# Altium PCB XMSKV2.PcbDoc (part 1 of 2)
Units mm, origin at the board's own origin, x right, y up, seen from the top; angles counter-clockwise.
Board outline 142.11 x 151.76 mm, 2 copper layers (Top Layer, Bottom Layer); 107 components, 86 nets, 501 pads, 0 vias.
Unrouted connection lines stored in the file: 29.
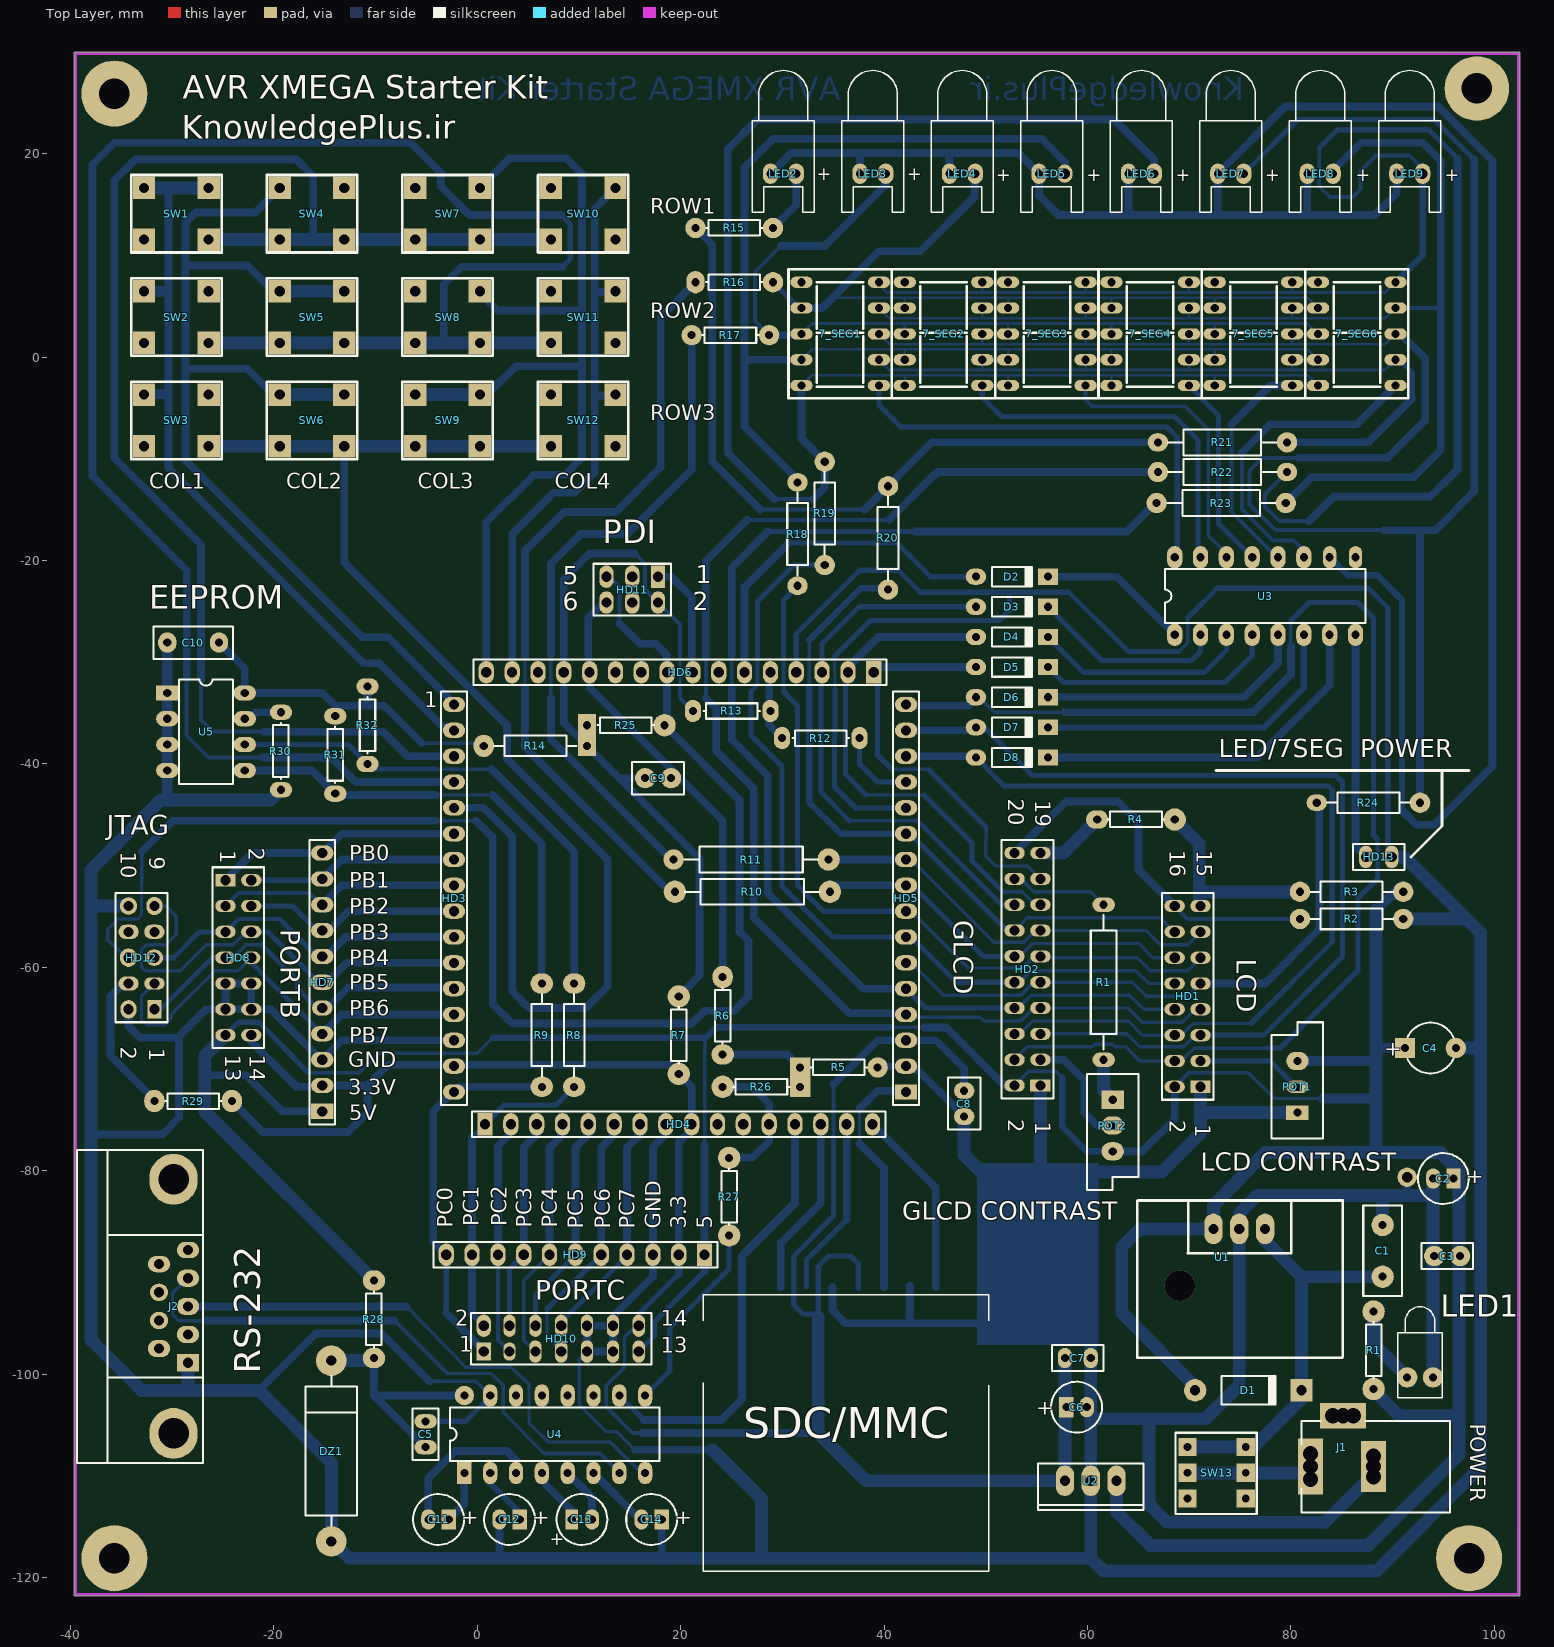
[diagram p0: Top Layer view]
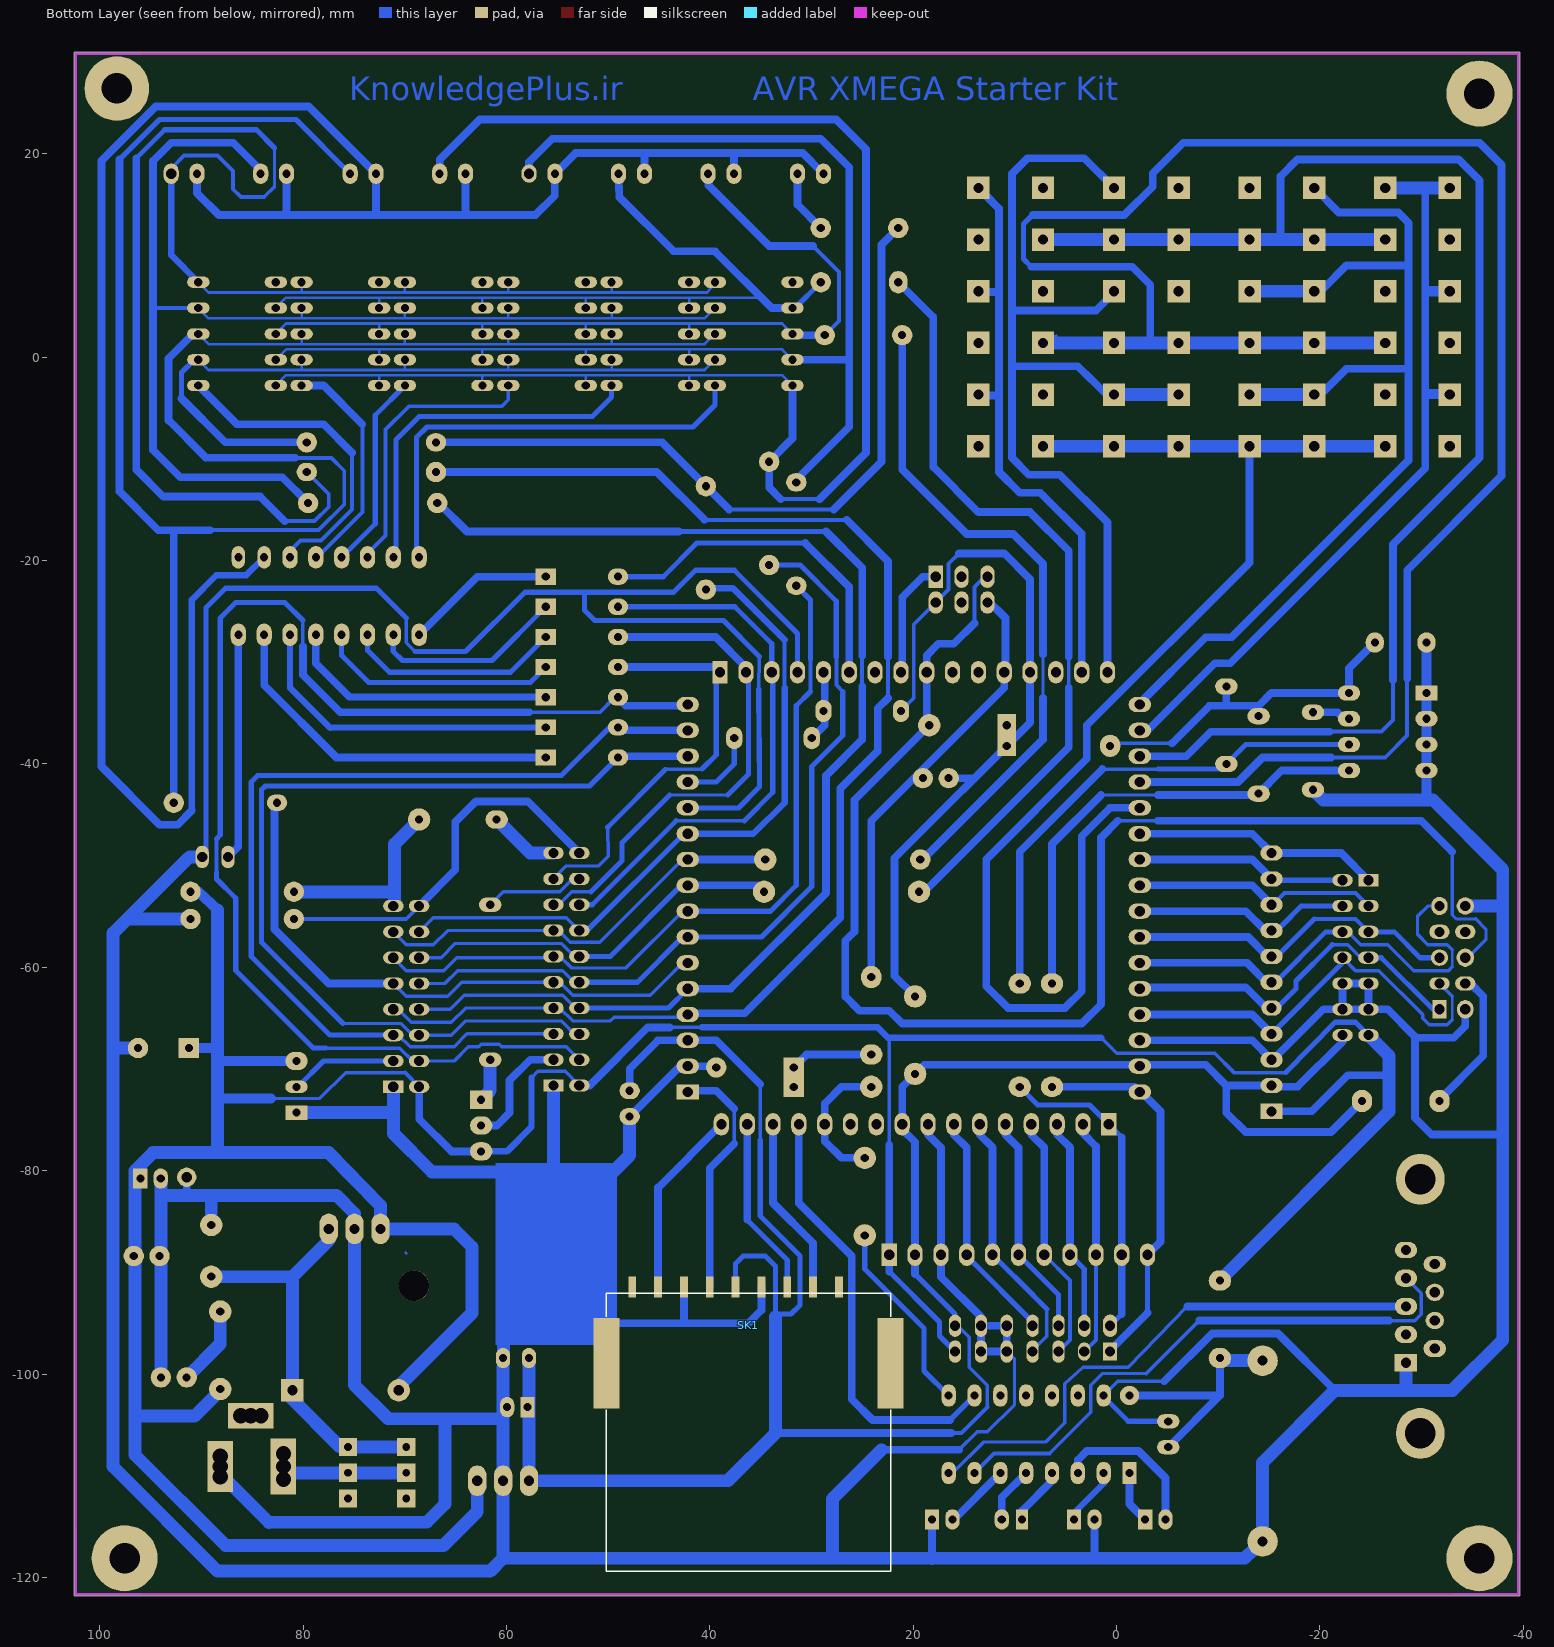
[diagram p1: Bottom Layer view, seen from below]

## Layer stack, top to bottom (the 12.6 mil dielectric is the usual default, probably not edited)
Top Layer: signal copper 0.0356
Dielectric: dielectric 0.32, FR-4, Dk 4.8
Bottom Layer: signal copper 0.0356

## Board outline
-39.624,-121.793 102.489,-121.793 102.489,29.972 -39.624,29.972

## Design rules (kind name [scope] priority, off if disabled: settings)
Clearance [All] p1: gap=0.254
PlaneClearance PlaneClearance_1 [HasPad('SW13-0')] p1: clearance=0.254
PlaneClearance [All] p2: clearance=0.508
PolygonConnect [All] p1: connectstyle=Relief reliefconductorwidth=0.254 reliefentries=4 polygonreliefangle="90 Angle" airgapwidth=0.254
RoutingPriority [All] p1: routingpriority=4
RoutingVias [All] p1: holewidth=0.508 width=1.27 viastyle="Through Hole" minholewidth=0.711 minwidth=1.27 maxholewidth=0.711 maxwidth=1.27
SolderMaskExpansion SolderMaskExpansion_1 [HasPad('SW13-0')] p1: expansion=0.051
SolderMaskExpansion [All] p2: expansion=0.102
Width [All] p1: maxlimit=2.54 minlimit=2.54 preferedwidth=0.254
26 further rules are at their usual default settings.

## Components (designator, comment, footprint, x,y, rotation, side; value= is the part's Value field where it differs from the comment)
7_SEG1 "Common cathode" 7_SEG 31.877,7.366 r0 top
7_SEG2 "Common cathode" 7_SEG 42.037,7.366 r0 top
7_SEG3 "Common cathode" 7_SEG 52.197,7.366 r0 top
7_SEG4 "Common cathode" 7_SEG 62.357,7.366 r0 top
7_SEG5 "Common cathode" 7_SEG 72.517,7.366 r0 top
7_SEG6 "Common cathode" 7_SEG 82.677,7.366 r0 top
C1 "330nF" RAD-0.2 89.027,-87.884 r270 top
C2 "10uF/16v/Tantalium" CAPPR2-5X6.8#1 94.996,-80.772 r180 top
C3 "100nF" RAD-0.1#1 95.377,-88.392 r180 top
C4 "1000uF/16v" CAPPR5-5X5 93.726,-67.945 r0 top
C5 "100nF" RAD-0.1#2 -5.08,-105.918 r90 top
C6 "10uF/16v/Tantalium" CAPPR2-5X6.8#1 58.928,-103.251 r0 top
C7 "100nF" RAD-0.1#3 59.055,-98.425 r0 top
C8 "100nF" CAPR2.54-5.1#1 47.879,-73.406 r270 top
C9 "100nF" CAPR2.54-5.1#2 17.78,-41.402 r180 top
C10 "100nF" CAPR5.08-7.8 -27.94,-28.067 r180 top
C11 "1uF" CAPPR2-5X6.8#1 -3.81,-114.3 r180 top
C12 "1uF" CAPPR2-5X6.8#1 3.175,-114.3 r180 top
C13 "1uF" CAPPR2-5X6.8#2 10.287,-114.3 r0 top
C14 "1uF" CAPPR2-5X6.8#1 17.145,-114.3 r180 top
D1 "1N4001" DIO10.46-5.3 75.819,-101.6 r0 top
D2 "1N4148" DIO7.1-3.9x1#1 52.578,-21.59 r0 top
D3 "1N4148" DIO7.1-3.9x1#1 52.578,-24.553 r0 top
D4 "1N4148" DIO7.1-3.9x1#1 52.578,-27.517 r0 top
D5 "1N4148" DIO7.1-3.9x1#1 52.578,-30.48 r0 top
D6 "1N4148" DIO7.1-3.9x1#1 52.578,-33.443 r0 top
D7 "1N4148" DIO7.1-3.9x1#2 52.578,-36.407 r0 top
D8 "1N4148" DIO7.1-3.9x1#1 52.578,-39.37 r0 top
DZ1 "1N4735" DIODE-0.7 -14.351,-107.569 r90 top
HD1 "2x8 box header" HDR2X8 71.12,-71.755 r90 top
HD2 "2x10 box header" HDR2X10 55.372,-71.628 r90 top
HD3 "1x16 female pin header" header1x16#1 -2.286,-34.163 r90 top
HD4 "1x16 female pin header" header1x16#2 0.762,-75.438 r180 top
HD5 "1x16 female pin header" header1x16#2 42.164,-72.263 r270 top
HD6 "1x16 female pin header" header1x16#2 38.989,-30.988 r0 top
HD7 "1x11 round pin Header" HDR1X11#1 -15.24,-74.168 r90 top
HD8 "2x7 pin header" HDR2X7#1 -24.765,-51.435 r270 top
HD9 "1x11 round pin Header" HDR1X11#2 22.352,-88.265 r180 top
HD10 "2x7 pin header" HDR2X7#2 0.635,-97.79 r0 top
HD11 "2x3 box header" HDR2X3 17.78,-21.59 r180 top
HD12 "2x5 box header" HDR2X5 -31.75,-64.135 r90 top
HD13 "1x2 pin header + jumper" RAD-0.1#4 88.646,-49.149 r180 top
J1 "Adaptor jack" KLD-0202 95.631,-109.093 r180 top
J2 "9 pin male D-Connector" DSUB1.385-2H -39.37,-93.345 r90 top
LED1 "LED" LED-1 92.71,-100.33 r90 top
LED2 "LED" LED-0#1 30.099,18.034 r180 top
LED3 "LED" LED-0#1 38.898,18.034 r180 top
LED4 "LED" LED-0#1 47.698,18.034 r180 top
LED5 "LED" LED-0#2 56.497,18.034 r180 top
LED6 "LED" LED-0#1 65.296,18.034 r180 top
LED7 "LED" LED-0#1 74.095,18.034 r180 top
LED8 "LED" LED-0#1 82.895,18.034 r180 top
LED9 "LED" LED-0#3 91.694,18.034 r180 top
POT1 "20K Multiturn" VR5#1 80.645,-71.755 r90 top
POT2 "20K Multiturn" VR5#2 62.484,-75.565 r270 top
R1 "470 ohm" AXIAL-0.3#1 88.138,-97.663 r270 top
R1 "0 ohm" AXIAL-0.6#1 61.595,-61.468 r90 top
R2 "0 ohm" AXIAL-0.4#1 85.979,-55.245 r180 top
R3 "0 ohm" AXIAL-0.4#1 85.979,-52.578 r180 top
R4 "0 ohm" AXIAL-0.3#2 64.77,-45.466 r0 top
R5 "0 ohm" AXIAL-0.3#3 35.56,-69.85 r0 top
R6 "0 ohm" AXIAL-0.3#4 24.13,-64.77 r90 top
R7 "0 ohm" AXIAL-0.3#1 19.812,-66.675 r90 top
R8 "0 ohm" AXIAL-0.4#2 9.525,-66.675 r90 top
R9 "0 ohm" AXIAL-0.4#2 6.35,-66.675 r90 top
R10 "0 ohm" AXIAL-0.6#2 27.051,-52.578 r0 top
R11 "0 ohm" AXIAL-0.6#3 26.924,-49.403 r0 top
R12 "0 ohm" AXIAL-0.3#5 33.782,-37.465 r180 top
R13 "0 ohm" AXIAL-0.3#5 25.019,-34.798 r180 top
R14 "0 ohm" AXIAL-0.4#3 5.715,-38.227 r180 top
R15 "0 ohm" AXIAL-0.3#6 25.273,12.7 r0 top
R16 "82 ohm" AXIAL-0.3#7 25.273,7.366 r0 top
R17 "82 ohm" AXIAL-0.3#6 24.892,2.159 r0 top
R18 "82 ohm" AXIAL-0.4#4 31.496,-17.399 r90 top
R19 "82 ohm" AXIAL-0.4#1 34.163,-15.367 r90 top
R20 "82 ohm" AXIAL-0.4#1 40.386,-17.78 r90 top
R21 "0 ohm" AXIAL-0.5#1 73.279,-8.382 r0 top
R22 "82 ohm" AXIAL-0.5#2 73.279,-11.303 r0 top
R23 "82 ohm" AXIAL-0.5#3 73.152,-14.351 r0 top
R24 "82 ohm" AXIAL-0.4#5 87.63,-43.815 r0 top
R25 "10Kohm" AXIAL-0.3#8 14.605,-36.195 r180 top
R26 "1Kohm" AXIAL-0.3#9 27.94,-71.755 r0 top
R27 "560 ohm" AXIAL-0.3#1 24.765,-82.55 r90 top
R28 "0 ohm" AXIAL-0.3#10 -10.16,-94.615 r90 top
R29 "0 ohm" AXIAL-0.3#10 -27.94,-73.152 r180 top
R30 "0 ohm" AXIAL-0.3#11 -19.304,-38.735 r270 top
R31 "3.3Kohm" AXIAL-0.3#5 -13.97,-39.116 r90 top
R32 "3.3Kohm" AXIAL-0.3#5 -10.795,-36.195 r90 top
SK1 "mmc socket" SDC 29.845,-91.44 r180 bottom
SW1 "Push button" SW_P_B -25.781,11.557 r180 top
SW2 "Push button" SW_P_B -25.781,1.397 r180 top
SW3 "Push button" SW_P_B -25.781,-8.763 r180 top locked
SW4 "Push button" SW_P_B -12.446,11.557 r180 top
SW5 "Push button" SW_P_B -12.446,1.397 r180 top
SW6 "Push button" SW_P_B -12.446,-8.763 r180 top
SW7 "Push button" SW_P_B 0.889,11.557 r180 top
SW8 "Push button" SW_P_B 0.889,1.397 r180 top
SW9 "Push button" SW_P_B 0.889,-8.763 r180 top
SW10 "Push button" SW_P_B 14.224,11.557 r180 top
SW11 "Push button" SW_P_B 14.224,1.397 r180 top
SW12 "Push button" SW_P_B 14.224,-8.763 r180 top
SW13 "6pin push button" "6PIN PB" 69.85,-112.268 r0 top
U1 "7805 + Heatsink" 7805_H 77.47,-85.725 r180 top
U2 "LF33" ISOWATT220AB 60.325,-110.49 r180 top
U3 "ULN2003A" A16 77.47,-23.495 r0 top
U4 "MAX232" DIP-16 7.62,-105.918 r0 top
U5 "AT24c64 + socket8" 8P3 -26.67,-36.83 r270 top

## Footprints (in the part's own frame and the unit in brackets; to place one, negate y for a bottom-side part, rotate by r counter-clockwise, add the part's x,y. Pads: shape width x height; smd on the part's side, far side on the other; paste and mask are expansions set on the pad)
"6PIN PB" [mil]
  rect 70x70 hole 30: 0(0,0.79) 0(0,100.79) 0(0,200.79) 0(225,0.79) 0(225,100.79) 0(225,200.79)
  silkscreen extent -47,-59 268,256
7_SEG [mm]
  oval 2.2x1.1 hole 0.8: 1(0,0) 2(0,-2.54) 3(0,-5.08) 4(0,-7.62) 5(0,-10.16) 6(7.62,-10.16) 7(7.62,-7.62) 8(7.62,-5.08) 9(7.62,-2.54) 10(7.62,0)
  silkscreen extent -1.27,-11.43 8.89,1.27
8P3 [mm]
  rect 1.5x2.2 hole 0.8: 1(-3.81,-3.81)
  oval 1.5x2.2 hole 0.8: 2(-1.27,-3.81) 3(1.27,-3.81) 4(3.81,-3.81) 5(3.81,3.81) 6(1.27,3.81) 7(-1.27,3.81) 8(-3.81,3.81)
  silkscreen extent -5.15,-2.65 5.15,2.65
7805_H [mm]
  round 3 hole 3: 0(8.382,5.588)
  oval 1.8x3 hole 1: 1(0,0) 2(5.08,0) 3(2.54,0)
  Multi-Layer lines w0.254: 7.62,2.388 7.569,2.337
  silkscreen extent -7.62,-2.82 12.57,12.67
A16 [mm]
  oval 1.5x2.2 hole 0.8: 1(-8.89,-3.81) 2(-6.35,-3.81) 3(-3.81,-3.81) 4(-1.27,-3.81) 5(1.27,-3.81) 6(3.81,-3.81) 7(6.35,-3.81) 8(8.89,-3.81) 11(3.81,3.81) 12(1.27,3.81) 13(-1.27,3.81) 14(-3.81,3.81) 15(-6.35,3.81) 16(-8.89,3.81)
  oval 1.3x2.2 hole 0.8: 9(8.89,3.81) 10(6.35,3.81)
  silkscreen extent -9.85,-2.65 9.85,2.65
AXIAL-0.3#1 [mm]
  round 2.2 hole 0.8: 1(-3.81,0) 2(3.81,0)
  silkscreen extent -2.77,-0.76 2.77,0.76
AXIAL-0.3#2 [mm]
  oval 2.2x1.8 hole 0.8: 1(-3.81,0)
  round 2.2 hole 0.8: 2(3.81,0)
  silkscreen extent -2.77,-0.76 2.77,0.76
AXIAL-0.3#3 [mm]
  rect 2x2 hole 0.8: 1(-3.81,0)
  round 2 hole 0.8: 2(3.81,0)
  silkscreen extent -2.77,-0.76 2.77,0.76
AXIAL-0.3#4 [mm]
  oval 2x2.2 hole 0.8: 1(-3.81,0)
  oval 2.2x2 hole 0.8: 2(3.81,0)
  silkscreen extent -2.77,-0.76 2.77,0.76
AXIAL-0.3#5 [mm]
  oval 1.6x2.2 hole 0.8: 1(-3.81,0) 2(3.81,0)
  silkscreen extent -2.77,-0.76 2.77,0.76
AXIAL-0.3#6 [mm]
  round 2 hole 0.8: 1(-3.81,0) 2(3.81,0)
  silkscreen extent -2.77,-0.76 2.77,0.76
AXIAL-0.3#7 [mm]
  oval 1.8x2.2 hole 0.8: 1(-3.81,0)
  round 2 hole 0.8: 2(3.81,0)
  silkscreen extent -2.77,-0.76 2.77,0.76
AXIAL-0.3#8 [mm]
  round 2.2 hole 0.8: 1(-3.81,0)
  rect 1.8x2.2 hole 0.8: 2(3.81,0)
  silkscreen extent -2.77,-0.76 2.77,0.76
AXIAL-0.3#9 [mm]
  round 2.2 hole 0.8: 1(-3.81,0)
  rect 2x2 hole 0.8: 2(3.81,0)
  silkscreen extent -2.77,-0.76 2.77,0.76
AXIAL-0.3#10 [mm]
  oval 2x2.2 hole 0.8: 1(-3.81,0) 2(3.81,0)
  silkscreen extent -2.77,-0.76 2.77,0.76
AXIAL-0.3#11 [mm]
  oval 1.5x2.2 hole 0.8: 1(-3.81,0) 2(3.81,0)
  silkscreen extent -2.77,-0.76 2.77,0.76
AXIAL-0.4#1 [mm]
  round 2 hole 0.8: 1(-5.08,0) 2(5.08,0)
  silkscreen extent -4.06,-1.02 4.06,1.02
AXIAL-0.4#2 [mm]
  oval 2x2.2 hole 0.8: 1(-5.08,0) 2(5.08,0)
  silkscreen extent -4.06,-1.02 4.06,1.02
AXIAL-0.4#3 [mm]
  rect 1.8x2 hole 0.8: 1(-5.08,0)
  oval 2x2.2 hole 0.8: 2(5.08,0)
  silkscreen extent -4.06,-1.02 4.06,1.02
AXIAL-0.4#4 [mm]
  oval 1.8x2 hole 0.8: 1(-5.08,0) 2(5.08,0)
  silkscreen extent -4.06,-1.02 4.06,1.02
AXIAL-0.4#5 [mm]
  oval 2x1.6 hole 0.8: 1(-5.08,0)
  round 2 hole 0.8: 2(5.08,0)
  silkscreen extent -4.06,-1.02 4.06,1.02
AXIAL-0.5#1 [mm]
  oval 2x1.8 hole 0.8: 1(-6.35,0)
  round 2 hole 0.8: 2(6.35,0)
  silkscreen extent -5.33,-1.27 5.33,1.27
AXIAL-0.5#2 [mm]
  round 2 hole 0.8: 1(-6.35,0)
  oval 2x1.8 hole 0.8: 2(6.35,0)
  silkscreen extent -5.33,-1.27 5.33,1.27
AXIAL-0.5#3 [mm]
  round 2 hole 0.8: 1(-6.35,0) 2(6.35,0)
  silkscreen extent -5.33,-1.27 5.33,1.27
AXIAL-0.6#1 [mm]
  oval 1.4x2.2 hole 0.8: 1(-7.62,0) 2(7.62,0)
  silkscreen extent -6.6,-1.27 6.6,1.27
AXIAL-0.6#2 [mm]
  round 2.2 hole 0.8: 1(-7.62,0) 2(7.62,0)
  silkscreen extent -6.6,-1.27 6.6,1.27
AXIAL-0.6#3 [mm]
  round 2 hole 0.8: 1(-7.62,0)
  round 2.2 hole 0.8: 2(7.62,0)
  silkscreen extent -6.6,-1.27 6.6,1.27
CAPPR2-5X6.8#1 [mm]
  rect 1.4x2 hole 0.8: 1(-1,0)
  oval 1.4x2 hole 0.8: 2(1,0)
  silkscreen extent -2.5,-2.5 2.5,2.5
CAPPR2-5X6.8#2 [mm]
  rect 1.2x2 hole 0.8: 1(-1,0)
  oval 1.4x2 hole 0.8: 2(1,0)
  silkscreen extent -2.5,-2.5 2.5,2.5
CAPPR5-5X5 [mm]
  rect 2x2 hole 0.8: 1(-2.5,0)
  round 2 hole 0.8: 2(2.5,0)
  silkscreen extent -2.26,-2.5 2.27,2.5
CAPR2.54-5.1#1 [mm]
  oval 1.65x2 hole 0.8: 1(-1.27,0) 2(1.27,0)
  silkscreen extent -2.55,-1.6 2.55,1.6
CAPR2.54-5.1#2 [mm]
  round 2 hole 0.8: 1(-1.27,0) 2(1.27,0)
  silkscreen extent -2.55,-1.6 2.55,1.6
CAPR5.08-7.8 [mm]
  oval 1.8x2 hole 0.8: 1(-2.54,0) 2(2.54,0)
  silkscreen extent -3.9,-1.6 3.9,1.6
DIO7.1-3.9x1#1 [mm]
  oval 2x1.6 hole 0.8: 1(-3.55,0)
  rect 2x1.6 hole 0.8: 2(3.55,0)
  silkscreen extent -1.95,-0.95 2.05,0.95
DIO7.1-3.9x1#2 [mm]
  oval 2x1.6 hole 0.8: 1(-3.55,0)
  rect 2x1.5 hole 0.8: 2(3.55,0)
  silkscreen extent -1.95,-0.95 2.05,0.95
DIO10.46-5.3 [mm]
  round 2.2 hole 1: 1(-5.23,0)
  rect 2.2x2.2 hole 1: 2(5.23,0)
  silkscreen extent -2.65,-1.4 2.75,1.4
DIODE-0.7 [mm]
  round 3 hole 1: 1(-8.89,0) 2(8.89,0)
  silkscreen extent -7.37,-2.54 7.37,2.54
DIP-16 [mm]
  rect 1.4x2.2 hole 0.8: 1(-8.89,-3.81)
  oval 1.4x2.2 hole 0.8: 2(-6.35,-3.81) 3(-3.81,-3.81) 4(-1.27,-3.81) 5(1.27,-3.81) 6(3.81,-3.81) 7(6.35,-3.81) 8(8.89,-3.81) 9(8.89,3.81) 10(6.35,3.81) 11(3.81,3.81) 12(1.27,3.81) 13(-1.27,3.81) 14(-3.81,3.81) 15(-6.35,3.81)
  round 1.9 hole 0.8: 16(-8.89,3.81)
  silkscreen extent -10.3,-2.65 10.3,2.65
DSUB1.385-2H [mm]
  oval 5x4.76 hole 3: 0(-12.495,-9.5) 0(12.495,-9.5)
  oval 1.6x2.2 hole 1: 1(5.54,-10.92) 6(4.155,-8.08)
  oval 1.69x2.2 hole 1: 2(2.77,-10.92) 3(0,-10.92) 4(-2.77,-10.92) 9(-4.155,-8.08)
  rect 1.69x2.2 hole 1: 5(-5.54,-10.92)
  oval 1.69x1.8 hole 1: 7(1.385,-8.08) 8(-1.385,-8.08)
  silkscreen extent -15.4,-12.4 15.4,0
HDR1X11#1 [mm]
  rect 1.5x2.2 hole 1: 1(0,0)
  oval 1.5x2.2 hole 1: 2(2.54,0) 3(5.08,0) 4(7.62,0) 6(12.7,0) 7(15.24,0) 8(17.78,0) 9(20.32,0) 10(22.86,0) 11(25.4,0)
  oval 1.5x2 hole 1: 5(10.16,0)
  silkscreen extent -1.27,-1.27 26.67,1.27
HDR1X11#2 [mm]
  rect 1.5x2.2 hole 1: 1(0,0)
  oval 1.5x2.2 hole 1: 2(2.54,0) 3(5.08,0) 4(7.62,0) 5(10.16,0) 6(12.7,0) 7(15.24,0) 8(17.78,0) 9(20.32,0) 10(22.86,0) 11(25.4,0)
  silkscreen extent -1.27,-1.27 26.67,1.27
HDR2X3 [mm]
  rect 1.4x2.2 hole 1: 1(0,0)
  oval 1.4x2.2 hole 1: 2(0,2.54) 3(2.54,0) 4(2.54,2.54) 5(5.08,0) 6(5.08,2.54)
  silkscreen extent -1.27,-1.27 6.35,3.81
HDR2X5 [mm]
  rect 1.8x1.4 hole 1: 1(0,0)
  oval 1.8x1.6 hole 1: 2(0,2.54) 9(10.16,0)
  oval 1.2x2 hole 1: 3(2.54,0)
  oval 1.4x2 hole 1: 4(2.54,2.54) 7(7.62,0) 8(7.62,2.54)
  oval 1.6x1.7 hole 1: 5(5.08,0)
  oval 1.8x1.7 hole 1: 6(5.08,2.54)
  oval 1.727x1.7 hole 1: 10(10.16,2.54)
  silkscreen extent -1.27,-1.27 11.43,3.81
HDR2X7#1 [mm]
  rect 1.2x2 hole 1: 1(0,0)
  oval 1.2x2 hole 1: 2(0,2.54) 3(2.54,0) 4(2.54,2.54) 5(5.08,0) 6(5.08,2.54) 7(7.62,0) 9(10.16,0) 10(10.16,2.54) 11(12.7,0) 12(12.7,2.54) 13(15.24,0) 14(15.24,2.54)
  oval 1.2x1.8 hole 1: 8(7.62,2.54)
  silkscreen extent -1.27,-1.27 16.51,3.81
HDR2X7#2 [mm]
  rect 1.4x1.8 hole 1: 1(0,0)
  oval 1.4x2.2 hole 1: 2(0,2.54)
  oval 1.2x1.8 hole 1: 3(2.54,0)
  oval 1.2x2.2 hole 1: 4(2.54,2.54) 5(5.08,0) 6(5.08,2.54) 7(7.62,0) 8(7.62,2.54) 9(10.16,0) 10(10.16,2.54) 11(12.7,0) 12(12.7,2.54) 13(15.24,0) 14(15.24,2.54)
  silkscreen extent -1.27,-1.27 16.51,3.81
HDR2X8 [mm]
  rect 1.2x2 hole 1: 1(0,0)
  oval 1.2x2 hole 1: 2(0,2.54) 3(2.54,0) 4(2.54,2.54) 5(5.08,0) 6(5.08,2.54) 7(7.62,0) 9(10.16,0) 10(10.16,2.54) 11(12.7,0) 13(15.24,0) 14(15.24,2.54) 15(17.78,0) 16(17.78,2.54)
  silkscreen extent -1.27,-1.27 19.05,3.81
HDR2X10 [mm]
  rect 1.2x2 hole 1: 1(0,0)
  oval 1.2x2 hole 1: 2(0,2.54) 3(2.54,0) 4(2.54,2.54) 5(5.08,0) 6(5.08,2.54) 7(7.62,0) 9(10.16,0) 10(10.16,2.54) 11(12.7,0) 13(15.24,0) 14(15.24,2.54) 15(17.78,0) 16(17.78,2.54) 17(20.32,0) 18(20.32,2.54) 19(22.86,0) 20(22.86,2.54)
  silkscreen extent -1.27,-1.27 24.13,3.81
header1x16#1 [mm]
  oval 1.5x2.2 hole 1: 1(0,0) 2(-2.54,0) 3(-5.08,0) 4(-7.62,0) 5(-10.16,0) 6(-12.7,0) 7(-15.24,0) 8(-17.78,0) 9(-20.32,0) 10(-22.86,0) 11(-25.4,0) 12(-27.94,0) 13(-30.48,0) 14(-33.02,0) 15(-35.56,0) 16(-38.1,0)
  silkscreen extent -39.37,-1.27 1.27,1.27
header1x16#2 [mm]
  rect 1.5x2.2 hole 1: 1(0,0)
  oval 1.5x2.2 hole 1: 2(-2.54,0) 3(-5.08,0) 4(-7.62,0) 5(-10.16,0) 6(-12.7,0) 7(-15.24,0) 8(-17.78,0) 9(-20.32,0) 10(-22.86,0) 11(-25.4,0) 12(-27.94,0) 13(-30.48,0) 14(-33.02,0) 15(-35.56,0) 16(-38.1,0)
  silkscreen extent -39.37,-1.27 1.27,1.27
ISOWATT220AB [mm]
  oval 1.8x3 hole 1: 1(-2.54,0) 2(2.54,0) 3(0,0)
  silkscreen extent -5.2,-1.7 5.2,2.9
KLD-0202 [mm]
  rect 2.5x2.5 hole 1.5: 1(13.7,0) 2(7.5,0) 3(10.5,-5) 3A(9.5,-5) 3B(11.5,-5)
  rect 2.5x3 hole 1.5: 1A(13.7,-1.25) 1B(13.7,1.25) 2A(7.5,-1) 2B(7.5,1)
  silkscreen extent 0,-4.5 14.6,4.5
LED-0#1 [mm]
  oval 1.5x2 hole 0.8: 1(1.27,0) 2(-1.27,0)
  silkscreen extent -3.05,-10.16 3.05,3.81
LED-0#2 [mm]
  oval 1.5x2 hole 0.8: 1(1.27,0)
  oval 1.5x1.778 hole 1: 2(-1.27,0)
  silkscreen extent -3.05,-10.16 3.05,3.81
LED-0#3 [mm]
  oval 1.5x2 hole 0.8: 1(1.27,0)
  oval 1.5x2 hole 1: 2(-1.27,0)
  silkscreen extent -3.05,-10.16 3.05,3.81
LED-1 [mm]
  round 2 hole 0.8: 1(0,1.27) 2(0,-1.27)
  silkscreen extent -2,-2.2 6.95,2.2
RAD-0.1#1 [mm]
  round 2 hole 0.8: 1(-1.27,0) 2(1.27,0)
  silkscreen extent -2.54,-1.27 2.54,1.27
RAD-0.1#2 [mm]
  oval 1.4x2.2 hole 0.8: 1(-1.27,0) 2(1.27,0)
  silkscreen extent -2.54,-1.27 2.54,1.27
RAD-0.1#3 [mm]
  oval 1.4x2 hole 0.8: 1(-1.27,0) 2(1.27,0)
  silkscreen extent -2.54,-1.27 2.54,1.27
RAD-0.1#4 [mm]
  oval 1.3x2.2 hole 1: 1(-1.27,0) 2(1.27,0)
  silkscreen extent -2.54,-1.27 2.54,1.27
RAD-0.2 [mm]
  round 2.2 hole 0.8: 1(-2.54,0) 2(2.54,0)
  silkscreen extent -4.44,-1.91 4.44,1.91
SDC [mil]
  rect 100x350 smd: 0(-800,-295) 0(300,-295)
  rect 30x80 smd: 1(0,0) 2(-100,0) 3(-200,0) 4(-300,0) 5(-400,0) 6(-500,0) 7(-600,0) 8(-700,0) 9(100,0)
  silkscreen extent -800,-1100 300,-25
SW_P_B [mm]
  rect 2.2x2.2 hole 1: 1(0.635,0) 2(0.635,-5.08) 3(6.985,-5.08) 4(6.985,0)
  silkscreen extent -0.64,-6.35 8.26,1.27
VR5#1 [mm]
  rect 1.4x2.2 hole 0.8: 1(-2.54,0)
  oval 1.2x2.2 hole 0.8: 2(0,0)
  oval 1.8x2.2 hole 0.8: 3(2.54,0)
  silkscreen extent -5.08,-2.54 6.35,2.54
VR5#2 [mm]
  rect 1.8x2.2 hole 0.8: 1(-2.54,0)
  oval 1.8x2.2 hole 0.8: 2(0,0) 3(2.54,0)
  silkscreen extent -5.08,-2.54 6.35,2.54

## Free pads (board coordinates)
  round 6.5 hole 3: 1(-35.687,-118.11) 2(97.536,-118.11) 4(-35.687,25.908)
  round 6.35 hole 3: 3(98.298,26.416)
  round 1.905 hole 1: 5(91.44,-80.645)
  oval 2x1.2 hole 1: 6(68.58,-64.135) 7(68.58,-59.055) 8(52.832,-64.008)
  oval 2x1.27 hole 1: 9(52.832,-58.928)

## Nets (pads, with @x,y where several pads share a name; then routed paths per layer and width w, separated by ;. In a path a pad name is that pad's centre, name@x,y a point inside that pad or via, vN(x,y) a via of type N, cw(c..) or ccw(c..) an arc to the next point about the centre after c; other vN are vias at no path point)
3.3V: C6.1 C7.1 C8.1 C9.2 C10.1 HD3.15 HD4.9 HD5.3 HD5.13 HD6.5 HD6.13 HD7.2 HD8.14 HD9.2 HD10.14 HD11.2 HD12.4 R7.1 R7.2 R12.1 R12.2 R13.1 R13.2 R14.1 R14.2 R25.2 R29.1 R29.2 R31.2 U2.2 U5.8 | length 365.6
  Bottom Layer w0.33: -5.461,-37.973 R14.2@0.254,-37.973 ; 12.7,-103.251 12.7,-101.092 14.478,-99.314 14.478,-96.393 HD10.14@15.875,-94.996 ; 19.939,-32.512 19.939,-29.464
  Bottom Layer w0.381: 12.7,-103.251 15.24,-105.791 16.256,-105.791 ; 15.494,-19.304 16.51,-20.32 16.51,-22.86 19.939,-26.289 19.939,-29.464 ; 19.939,-32.512 19.939,-33.528 R13.2@21.209,-34.798 ; 35.041,-76.973 35.041,-71.512
  Bottom Layer w0.508: -22.225,-67.31 HD8.14@-22.225,-66.675 ; HD10.14@15.875,-95.25 15.875,-94.107 19.812,-90.17 ; 33.528,-94.361 33.528,-89.408 34.544,-88.392 36.703,-88.392 37.465,-89.154 37.465,-91.567 ; 33.528,-94.107 32.004,-94.107 31.115,-93.218 31.115,-88.392 35.041,-84.466 35.041,-76.973 ; R12.1@37.592,-37.465 37.592,-40.005 39.37,-41.783 HD5.13@41.656,-41.783
  Bottom Layer w0.762: HD12.4@-34.29,-61.595 -34.798,-61.595 -36.068,-62.865 -36.068,-68.707 R29.2@-31.623,-73.152 ; C10.1@-25.4,-28.067 -22.86,-30.607 U5.8@-22.86,-33.02 -15.24,-33.02 -13.97,-34.29 -9.144,-34.29 -5.461,-37.973 ; R29.1@-24.13,-73.152 -21.082,-76.2 -12.7,-76.2 -10.795,-74.295 -10.795,-71.755 ; -22.225,-67.31 -17.78,-71.755 HD7.2@-15.24,-71.755 ; HD7.2@-15.24,-71.628 -10.795,-71.628 -8.763,-69.596 18.923,-69.596 R7.1@19.812,-70.485 21.082,-71.755 21.082,-75.946 19.812,-77.216 19.812,-90.17 ; R14.1@10.795,-38.227 R25.2@10.795,-36.195 ; 14.097,-41.402 C9.2@16.51,-41.402 ; 15.494,-19.304 11.049,-19.304 8.509,-21.844 8.509,-35.941 21.844,-49.276 21.844,-60.833 R7.2@19.812,-62.865 ; 16.256,-105.791 33.528,-105.791 ; HD6.5@28.702,-30.988 28.702,-36.195 R12.2@29.972,-37.465 ; 35.041,-71.512 39.37,-67.183 HD5.3@41.91,-67.183 ; HD5.3@42.164,-67.183 45.085,-67.183 47.879,-69.977 C8.1@47.879,-72.136
  Bottom Layer w1.27: 33.528,-94.361 33.528,-105.791 38.227,-110.49 U2.2@57.785,-110.49 ; U2.2@57.785,-110.363 C7.1@57.785,-98.425
5V: C2.1 C3.1 C4.1 C5.1 D1.1 DZ1.2 HD1.2 HD1.15 HD2.2 HD2.19 HD7.1 HD8.13 HD9.1 HD10.13 POT1.3 POT2.3 R1.2@88.138,-101.473 R3.1 R3.2 R4.1 R4.2 R28.1 R28.2 U1.2 U2.1 U4.16 | length 433.8
  Bottom Layer w0.33: -16.637,-70.358 -11.557,-70.358 ; -9.652,-68.453 0,-68.453 1.524,-66.929 ; 22.352,-77.47 22.352,-66.929 ; 40.767,-65.913 43.942,-65.913 ; HD2.2@52.832,-71.628 54.229,-70.231 56.896,-70.231 57.531,-70.866 ; 69.977,-70.358 75.819,-70.358 78.359,-72.898 83.185,-72.898
  Bottom Layer w0.381: -11.557,-70.358 -9.652,-68.453 ; HD1.2@68.58,-71.755 69.977,-70.358
  Bottom Layer w0.508: HD8.13@-24.765,-66.675 -23.495,-65.405 -21.463,-65.405 -16.637,-70.358 ; HD10.13@15.875,-97.79 17.399,-96.266 17.399,-94.869 22.352,-89.916
  Bottom Layer w0.635: 1.524,-66.929 22.479,-66.929 23.495,-65.913 40.767,-65.913 ; 51.816,-71.628 HD2.2@52.832,-71.628 ; 57.531,-70.866 57.531,-75.692 59.944,-78.105 POT2.3@61.849,-78.105
  Bottom Layer w0.762: -26.797,-70.612 -22.733,-70.612 -19.177,-74.168 HD7.1@-15.24,-74.168 ; R28.1@-10.16,-98.425 -10.16,-102.108 ; C5.1@-5.08,-107.188 -10.16,-102.108 ; U4.16@-1.27,-102.108 -10.16,-102.108 ; 22.352,-89.916 22.352,-77.47 ; 43.942,-65.913 46.101,-65.913 51.816,-71.628 ; POT2.3@62.484,-78.105 65.405,-78.105 68.58,-74.93 HD1.2@68.58,-71.755 ; U2.1@62.865,-110.211 U2.1@63.005,-110.35
  Bottom Layer w1.016: POT1.3@80.645,-69.215 88.265,-69.215 ; 83.185,-72.898 88.138,-72.898 ; 88.265,-67.945 C4.1@91.226,-67.945 ; 88.392,-54.356 90.297,-52.578 R3.1@91.313,-52.578
  Bottom Layer w1.27: HD8.13@-24.765,-66.675 -26.797,-68.707 -26.797,-74.168 R28.2@-10.16,-90.805 ; DZ1.2@-14.351,-98.679 R28.1@-10.16,-98.679 ; HD2.19@55.372,-48.768 57.658,-48.768 R4.1@60.96,-45.466 ; U2.1@62.865,-110.617 62.865,-113.538 66.167,-116.84 87.63,-116.84 96.52,-107.95 96.52,-80.01 94.742,-78.232 77.47,-78.232 72.39,-83.439 U1.2@72.39,-85.725 65.151,-85.725 63.373,-87.503 63.373,-93.98 D1.1@70.97,-101.6 ; R4.2@68.58,-45.466 70.993,-47.879 70.993,-52.578 ; HD1.15@70.993,-53.848 70.993,-52.578 ; R3.2@81.153,-52.578 70.993,-52.578 ; R1.2@88.392,-101.854 90.678,-104.14 96.52,-104.14 ; 88.392,-77.978 88.392,-54.356
7SEG_A: 7_SEG1.10 7_SEG2.10 7_SEG3.10 7_SEG4.10 7_SEG5.10 7_SEG6.10 LED9.2 R22.2 | length 156.6
  Bottom Layer w0.254: 7_SEG1.10@39.497,7.366 39.497,7.239 40.259,6.35 89.281,6.35 7_SEG6.10@90.297,7.366 ; 49.657,6.477 7_SEG2.10@49.657,7.366 ; 59.817,6.477 7_SEG3.10@59.817,7.366 ; 69.977,6.477 7_SEG4.10@69.977,7.366 ; 80.137,6.477 7_SEG5.10@80.137,7.366
  Bottom Layer w0.33: 82.804,20.574 82.804,16.764 83.82,15.748
  Bottom Layer w0.381: R22.2@79.629,-11.303 77.47,-13.462 77.47,-14.732 78.867,-16.129 81.788,-16.129 ; 83.82,15.748 86.106,15.748 86.868,16.51 86.868,18.288 88.392,19.812 91.694,19.812 92.71,18.796 LED9.2@92.964,18.796
  Bottom Layer w0.508: 82.804,20.574 84.582,22.352 93.599,22.352 96.393,19.558
  Bottom Layer w0.635: 7_SEG6.10@90.297,7.366 92.964,10.033 LED9.2@92.964,18.034
  Bottom Layer w0.762: 81.788,-16.129 84.201,-13.716 93.726,-13.716 96.393,-11.049 96.393,19.558
7SEG_B: 7_SEG1.9 7_SEG2.9 7_SEG3.9 7_SEG4.9 7_SEG5.9 7_SEG6.9 LED8.2 R23.2 | length 118.1
  Bottom Layer w0.254: 7_SEG1.9@39.497,4.826 40.513,3.81 89.281,3.81 7_SEG6.9@90.297,4.826 ; 49.657,3.81 7_SEG2.9@49.657,4.826 ; 59.817,3.81 7_SEG3.9@59.817,4.826 ; 69.977,3.81 7_SEG4.9@69.977,4.826 ; 80.137,3.81 7_SEG5.9@80.137,4.826
  Bottom Layer w0.381: 7_SEG6.9@90.678,4.826 94.488,4.826
  Bottom Layer w0.508: LED8.2@84.165,18.034 LED8.2@84.165,18.379
  Bottom Layer w0.762: R23.2@79.502,-14.351 82.042,-11.811 92.075,-11.811 94.742,-9.144 94.742,19.304 92.964,21.082 86.868,21.082 LED8.2@84.165,18.379
7SEG_C: 7_SEG1.8 7_SEG2.8 7_SEG3.8 7_SEG4.8 7_SEG5.8 7_SEG6.8 LED7.2 R24.2 | length 199
  Bottom Layer w0.254: 7_SEG1.8@39.497,2.286 40.513,1.27 89.281,1.27 7_SEG6.8@90.297,2.286 ; 49.657,1.27 7_SEG2.8@49.657,2.286 ; 59.817,1.27 7_SEG3.8@59.817,2.286 ; 69.977,1.27 7_SEG4.8@69.977,2.286 ; 80.137,1.27 7_SEG5.8@80.137,2.286
  Bottom Layer w0.381: 80.772,-9.906 77.216,-9.906 75.946,-11.176 75.946,-14.478 78.486,-17.018 89.408,-17.018
  Bottom Layer w0.508: LED7.2@75.365,18.034 80.699,23.368 94.107,23.368 98.044,19.431
  Bottom Layer w0.762: 80.772,-9.906 89.535,-9.906 93.218,-6.223 93.218,-0.127 7_SEG6.8@90.678,2.413 ; 89.154,-17.018 94.234,-17.018 98.044,-13.208 98.044,19.431 ; R24.2@92.71,-43.815 92.71,-17.018
7SEG_D: 7_SEG1.5 7_SEG2.5 7_SEG3.5 7_SEG4.5 7_SEG5.5 7_SEG6.5 LED6.2 R19.2 | length 154.4
  Bottom Layer w0.254: 7_SEG1.5@31.877,-2.794 32.893,-1.778 81.661,-1.778 7_SEG6.5@82.677,-2.794 ; 7_SEG2.5@42.037,-2.794 42.037,-1.778 ; 7_SEG3.5@52.197,-2.794 52.197,-1.778 ; 7_SEG4.5@62.357,-2.794 62.357,-1.905 ; 7_SEG5.5@72.517,-2.794 72.517,-1.778
  Bottom Layer w0.381: 29.21,-13.97 33.02,-13.97
  Bottom Layer w0.762: 29.21,-13.97 24.638,-9.398 24.638,20.447 27.559,23.368 62.611,23.368 66.548,19.431 LED6.2@66.566,18.034 ; 7_SEG1.5@31.877,-2.794 31.877,-8.001 R19.2@34.163,-10.287 34.163,-12.827 33.02,-13.97
7SEG_DP: 7_SEG1.7 7_SEG2.7 7_SEG3.7 7_SEG4.7 7_SEG5.7 7_SEG6.7 LED2.2 R15.1 R15.2 R20.2 R21.1 R21.2 | length 152.5
  Bottom Layer w0.254: 7_SEG1.7@39.497,-0.254 40.513,-1.27 89.281,-1.27 7_SEG6.7@90.297,-0.254 ; 49.657,-1.27 7_SEG2.7@49.657,-0.254 ; 59.817,-1.143 7_SEG3.7@59.817,-0.254 ; 69.977,-1.27 7_SEG4.7@69.977,-0.254 ; 80.137,-1.27 7_SEG5.7@80.137,-0.254
  Bottom Layer w0.381: 27.813,-14.986 38.1,-14.986
  Bottom Layer w0.508: 7_SEG6.7@90.678,-0.254 91.948,-1.524 91.948,-4.064
  Bottom Layer w0.762: R15.1@21.463,12.7 23.114,11.049 23.114,-10.287 27.813,-14.986 ; R15.2@29.083,12.7 31.369,14.986 LED2.2@31.369,18.034 ; 38.1,-14.986 44.704,-8.382 R21.1@66.929,-8.382 ; R21.2@79.629,-8.382 87.63,-8.382 91.948,-4.064
7SEG_E: 7_SEG1.4 7_SEG2.4 7_SEG3.4 7_SEG4.4 7_SEG5.4 7_SEG6.4 LED5.2 R18.2 | length 128.4
  Bottom Layer w0.254: 7_SEG1.4@31.877,-0.254 32.893,0.762 81.661,0.762 7_SEG6.4@82.677,-0.254 ; 7_SEG2.4@42.037,-0.254 42.037,0.635 ; 7_SEG3.4@52.197,-0.254 52.197,0.762 ; 7_SEG4.4@62.357,-0.254 62.357,0.635 ; 7_SEG5.4@72.517,-0.254 72.517,0.635
  Bottom Layer w0.762: 26.416,-0.254 7_SEG1.4@31.877,-0.254 ; R18.2@31.496,-12.065 26.289,-6.858 26.289,18.669 29.083,21.463 55.499,21.463 57.785,19.177 LED5.2@57.767,18.034
7SEG_F: 7_SEG1.2 7_SEG2.2 7_SEG3.2 7_SEG4.2 7_SEG5.2 7_SEG6.2 LED4.2 R16.2 | length 79.4
  Bottom Layer w0.254: 34.925,5.842 81.661,5.842 7_SEG6.2@82.677,4.826 ; 7_SEG2.2@42.037,4.826 42.037,5.715 ; 7_SEG3.2@52.197,4.826 52.197,5.715 ; 7_SEG4.2@62.357,4.826 62.357,5.715 ; 7_SEG5.2@72.517,4.826 72.517,5.715
  Bottom Layer w0.381: 7_SEG1.2@31.623,4.826 7_SEG1.2@31.877,4.826
  Bottom Layer w0.508: R16.2@29.083,7.366 7_SEG1.2@31.623,4.826
  Bottom Layer w0.762: 7_SEG1.2@31.877,4.826 33.909,4.826 39.497,10.414 43.561,10.414 48.895,15.748 LED4.2@48.968,18.034
7SEG_G: 7_SEG1.3 7_SEG2.3 7_SEG3.3 7_SEG4.3 7_SEG5.3 7_SEG6.3 LED3.2 R17.2 | length 83.1
  Bottom Layer w0.254: 7_SEG1.3@31.877,2.286 32.893,3.302 81.661,3.302 7_SEG6.3@82.677,2.286 ; 7_SEG2.3@42.037,2.286 42.037,3.302 ; 7_SEG3.3@52.197,2.286 52.197,3.302 ; 7_SEG4.3@62.357,2.286 62.357,3.302 ; 7_SEG5.3@72.517,2.286 72.517,3.175
  Bottom Layer w0.381: R17.2@28.702,2.159 27.305,3.556 27.305,8.382 29.845,10.922 ; 7_SEG1.3@31.75,2.159 7_SEG1.3@31.877,2.286
  Bottom Layer w0.762: R17.2@28.702,2.159 7_SEG1.3@31.75,2.159 ; 29.845,10.922 34.163,10.922 40.132,16.891 LED3.2@40.168,18.034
